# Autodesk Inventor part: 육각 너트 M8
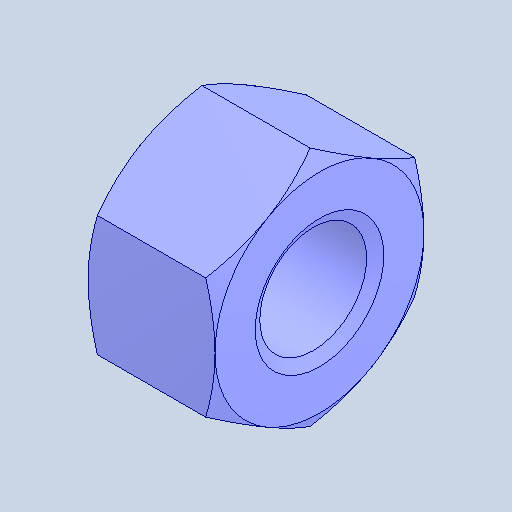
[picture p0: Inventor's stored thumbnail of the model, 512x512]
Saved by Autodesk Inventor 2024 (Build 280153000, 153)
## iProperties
Created: 2024-11
Part Number: 육각 너트 M8
Material: 강철, 연강
Description: 6각 너트 및 6각 가는 너트
Document SubType Name: Modeling
Designer: user
Density: 7.85 g/cm^3
Appearance: 기본값
Author: jhkim
Sending System: Autodesk Inventor 2025
Preprocessor: ST-DEVELOPER v20
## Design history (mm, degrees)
node "육각 너트 M81"
node "솔리드1"
body "Solid1"
